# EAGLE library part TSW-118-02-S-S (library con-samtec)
THROUGH-HOLE .025" SQ POST HEADER Source: Samtec TSW.pdf
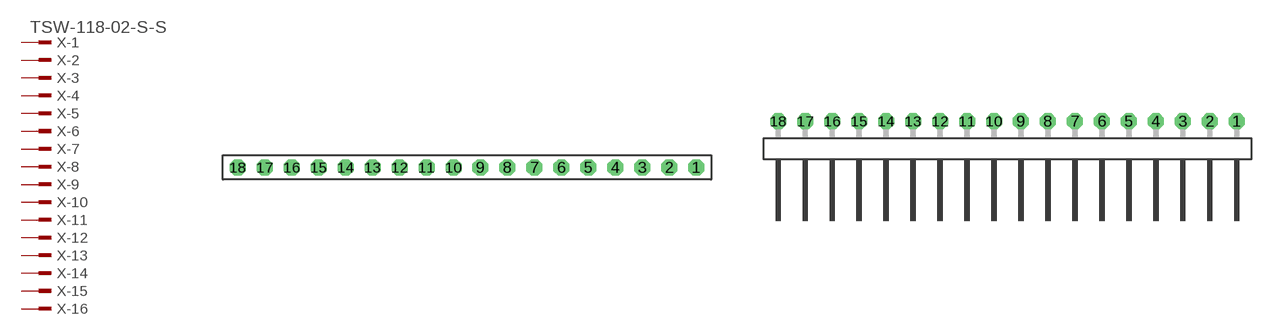
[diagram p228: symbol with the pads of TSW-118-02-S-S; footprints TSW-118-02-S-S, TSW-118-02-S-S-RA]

Designator prefix X; gates -1=MPINV -2=MPIN -3=MPIN -4=MPIN -5=MPIN -6=MPIN -7=MPIN -8=MPIN -9=MPIN -10=MPIN -11=MPIN -12=MPIN -13=MPIN -14=MPIN -15=MPIN -16=MPIN -17=MPIN -18=MPIN

## TSW-118-02-S-S (OC_FARNELL: unknown; OC_NEWARK: unknown)  [TSW-118-02-S-S]
1  -1:1  pas
2  -2:1  pas
3  -3:1  pas
4  -4:1  pas
5  -5:1  pas
6  -6:1  pas
7  -7:1  pas
8  -8:1  pas
9  -9:1  pas
10  -10:1  pas
11  -11:1  pas
12  -12:1  pas
13  -13:1  pas
14  -14:1  pas
15  -15:1  pas
16  -16:1  pas
17  -17:1  pas
18  -18:1  pas

## TSW-118-02-S-S-RA (OC_FARNELL: unknown; OC_NEWARK: unknown)  [TSW-118-02-S-S-RA]
Pads as for TSW-118-02-S-S

## Footprint TSW-118-02-S-S (pad centres in mm)
THROUGH-HOLE .025" SQ POST HEADER Source: Samtec TSW.pdf
drill 1 pad 1.5 octagon: 1 21.59,0; 2 19.05,0; 3 16.51,0; 4 13.97,0; 5 11.43,0; 6 8.89,0; 7 6.35,0; 8 3.81,0; 9 1.27,0; 10 -1.27,0; 11 -3.81,0; 12 -6.35,0; 13 -8.89,0; 14 -11.43,0; 15 -13.97,0; 16 -16.51,0; 17 -19.05,0; 18 -21.59,0

## Footprint TSW-118-02-S-S-RA (pad centres in mm)
THROUGH-HOLE .025" SQ POST HEADER Source: Samtec TSW.pdf
drill 1 pad 1.5 octagon: 1 21.59,1.524; 2 19.05,1.524; 3 16.51,1.524; 4 13.97,1.524; 5 11.43,1.524; 6 8.89,1.524; 7 6.35,1.524; 8 3.81,1.524; 9 1.27,1.524; 10 -1.27,1.524; 11 -3.81,1.524; 12 -6.35,1.524; 13 -8.89,1.524; 14 -11.43,1.524; 15 -13.97,1.524; 16 -16.51,1.524; 17 -19.05,1.524; 18 -21.59,1.524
